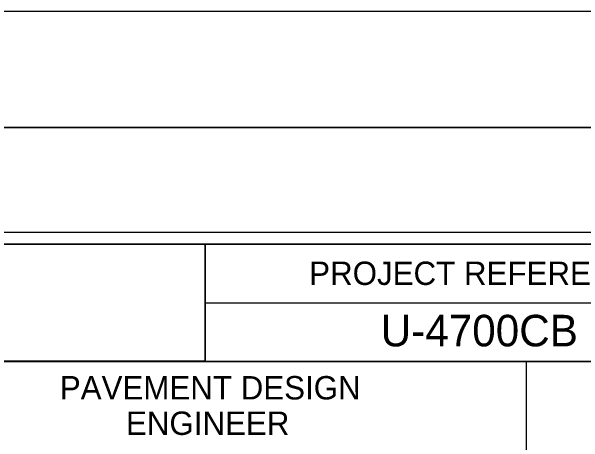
# Model space of a CAD drawing. Extents: x 2294342 to 2294901, y 719427 to 719941.
# Drawn here: x 2294739.63 to 2294764.08, y 719922.69 to 719941.13 of the extents above; entities that cross this region are included whole.
import ezdxf

# ---------------------------------------------------------------- set-up
doc = ezdxf.new("R2010")
doc.units = 0
for name, color, linetype in [('Default', 7, 'Continuous'), ('Sheet Data Field CELL', 7, 'Continuous'), ('Sheet Plan CELL', 7, 'Continuous'), ('Sheet Plot Border Inside CELL', 7, 'Continuous'), ('Sheet Plot Border Outside CELL', 7, 'Continuous'), ('Sheet Sticker Exception Certification CELL', 7, 'Continuous'), ('Sheet Typical CELL', 7, 'Continuous')]:
    doc.layers.add(name, color=color, linetype=linetype)

msp = doc.modelspace()

# ---------------------------------------------------------------- linework, layer by layer
at = {"layer": 'Default'}
msp.add_line((2294454.524, 719936.169), (2294794.524, 719936.169), dxfattribs=at)
msp.add_lwpolyline([(2294454.524, 719936.169), (2294794.524, 719936.169), (2294794.524, 719716.169), (2294454.524, 719716.169)], close=True, dxfattribs=at)
msp.add_lwpolyline([(2294454.524, 719936.169), (2294794.524, 719936.169), (2294794.524, 719716.169), (2294454.524, 719716.169)], close=True, dxfattribs=at)
at = {"layer": 'Sheet Plan CELL'}
for points in [[(2294761.64, 719903.659), (2294735.355, 719903.659), (2294735.355, 719926.159), (2294761.64, 719926.159)], [(2294787.924, 719903.659), (2294761.64, 719903.659), (2294761.64, 719926.159), (2294787.924, 719926.159)]]:
    msp.add_lwpolyline(points, dxfattribs=at)
at = {"layer": 'Sheet Plot Border Inside CELL'}
msp.add_lwpolyline([(2294790.424, 719931.679), (2294457.124, 719931.679), (2294457.124, 719720.659), (2294790.424, 719720.659)], close=True, dxfattribs=at)
at = {"layer": 'Sheet Plot Border Outside CELL'}
for points in [[(2294793.79, 719941.133), (2294456.99, 719941.133), (2294456.99, 719721.133), (2294793.79, 719721.133)], [(2294794.524, 719936.169), (2294454.524, 719936.169), (2294454.524, 719716.169), (2294794.524, 719716.169)]]:
    msp.add_lwpolyline(points, close=True, dxfattribs=at)
at = {"layer": 'Sheet Sticker Exception Certification CELL'}
for p, q in [((2294705.291, 719931.172), (2294747.914, 719931.172)), ((2294747.914, 719931.169), (2294747.914, 719926.162)), ((2294747.914, 719926.165), (2294705.291, 719926.165))]:
    msp.add_line(p, q, dxfattribs=at)
at = {"layer": 'Sheet Typical CELL'}
for p, q in [((2294747.914, 719928.659), (2294787.924, 719928.659)), ((2294747.914, 719926.159), (2294767.924, 719926.159))]:
    msp.add_line(p, q, dxfattribs=at)
for points in [[(2294787.924, 719931.169), (2294487.924, 719931.169), (2294487.924, 719721.169), (2294787.924, 719721.169)], [(2294747.914, 719931.169), (2294787.924, 719931.169), (2294787.924, 719926.159), (2294747.914, 719926.159)]]:
    msp.add_lwpolyline(points, close=True, dxfattribs=at)

# ---------------------------------------------------------------- texts
at = {"layer": 'Sheet Data Field CELL'}
msp.add_text('U-4700CB', height=1.35, rotation=360, dxfattribs=at).set_placement((2294755.408, 719926.802))
at = {"layer": 'Sheet Plan CELL'}
for s, height, p in [('PAVEMENT DESIGN', 1.00002, (2294741.699, 719924.531)), ('ENGINEER', 1, (2294744.524, 719923.013))]:
    msp.add_text(s, height=height, dxfattribs=at).set_placement(p)
at = {"layer": 'Sheet Typical CELL'}
msp.add_text('PROJECT REFERENCE NO.', height=1.00002, dxfattribs=at).set_placement((2294752.354, 719929.429))

doc.saveas('drawing.dxf')
